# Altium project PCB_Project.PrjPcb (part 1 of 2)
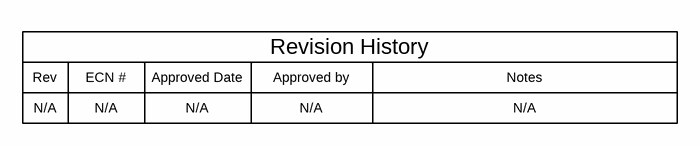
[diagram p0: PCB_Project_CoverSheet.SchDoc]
TID: TIDA-010080; TechSupport: http://www.ti.com/support; SCH_Rev: E1; PRJ_Title: Change in menu Project|Project Options|Parameters; PRJ_Number: TIDA-010080; PRJ_Engineer: Enter name of project lead; PRJ_Customer: Public Release; PCB_Rev: E1; Max Wang: Who did the Layout?; CopyrightYear: 2018
4 sheets, 183 parts. Net scope: global (net labels, ports and power ports of the same name join across sheets).
Board file: PCB_Project_PCB.PcbDoc
Sheets:
  PCB_Project_CoverSheet.SchDoc
  PFC.SchDoc
  LLC.SchDoc
  PCB_Project_EVM_Hardware.SchDoc

## Sheet PCB_Project_CoverSheet.SchDoc
size 431 x 279 mm; Date: Not shown in title block; ApprovedBy: Not shown in title block; CheckedBy: Not shown in title block; Author: Not shown in title block; CompanyName: Not shown in title block; Engineer: Not shown in title block; Organization: Not shown in title block; Address1: Not shown in title block; Address2: Not shown in title block; Address3: Not shown in title block; Address4: Not shown in title block; DocumentNumber: 1; Revision: Use project parameter SCH_Rev; SheetNumber: 1; SheetTotal: 3; PageSetup: Record=PageOptions¦CenterHorizontal=True¦CenterVertical=True¦PrintScale=1.00¦XCorrection=1.00¦YCorrection=1.00¦PrintKind=0¦BorderSize=5000000¦LeftOffset=0¦BottomOffset=0¦Orientation=2¦PaperLength=1000¦PaperWidth=1000¦Scale=100¦PaperSource=15¦PrintQuality=600¦MediaType=1¦DitherType=10¦PaperKind=Letter¦PrintScaleMode=1

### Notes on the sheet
- Rev
- N/A
- ECN #
- Approved Date
- Approved by
- Revision History
- Notes

## Sheet PFC.SchDoc
size 431 x 279 mm; Date: Not shown in title block; ApprovedBy: Not shown in title block; CheckedBy: Not shown in title block; Author: Not shown in title block; CompanyName: Not shown in title block; DrawnBy: Max Wang; Engineer: Max Wang; Organization: Not shown in title block; Address1: Not shown in title block; Address2: Not shown in title block; Address3: Not shown in title block; Address4: Not shown in title block; DocumentNumber: 1; Revision: Use project parameter SCH_Rev; SheetNumber: 2; SheetTotal: 3; PageSetup: Record=PageOptions¦CenterHorizontal=True¦CenterVertical=True¦PrintScale=1.00¦XCorrection=1.00¦YCorrection=1.00¦PrintKind=0¦BorderSize=5000000¦LeftOffset=0¦BottomOffset=0¦Orientation=2¦PaperLength=1000¦PaperWidth=1000¦Scale=100¦PaperSource=15¦PrintQuality=600¦MediaType=1¦DitherType=10¦PaperKind=Letter¦PrintScaleMode=1
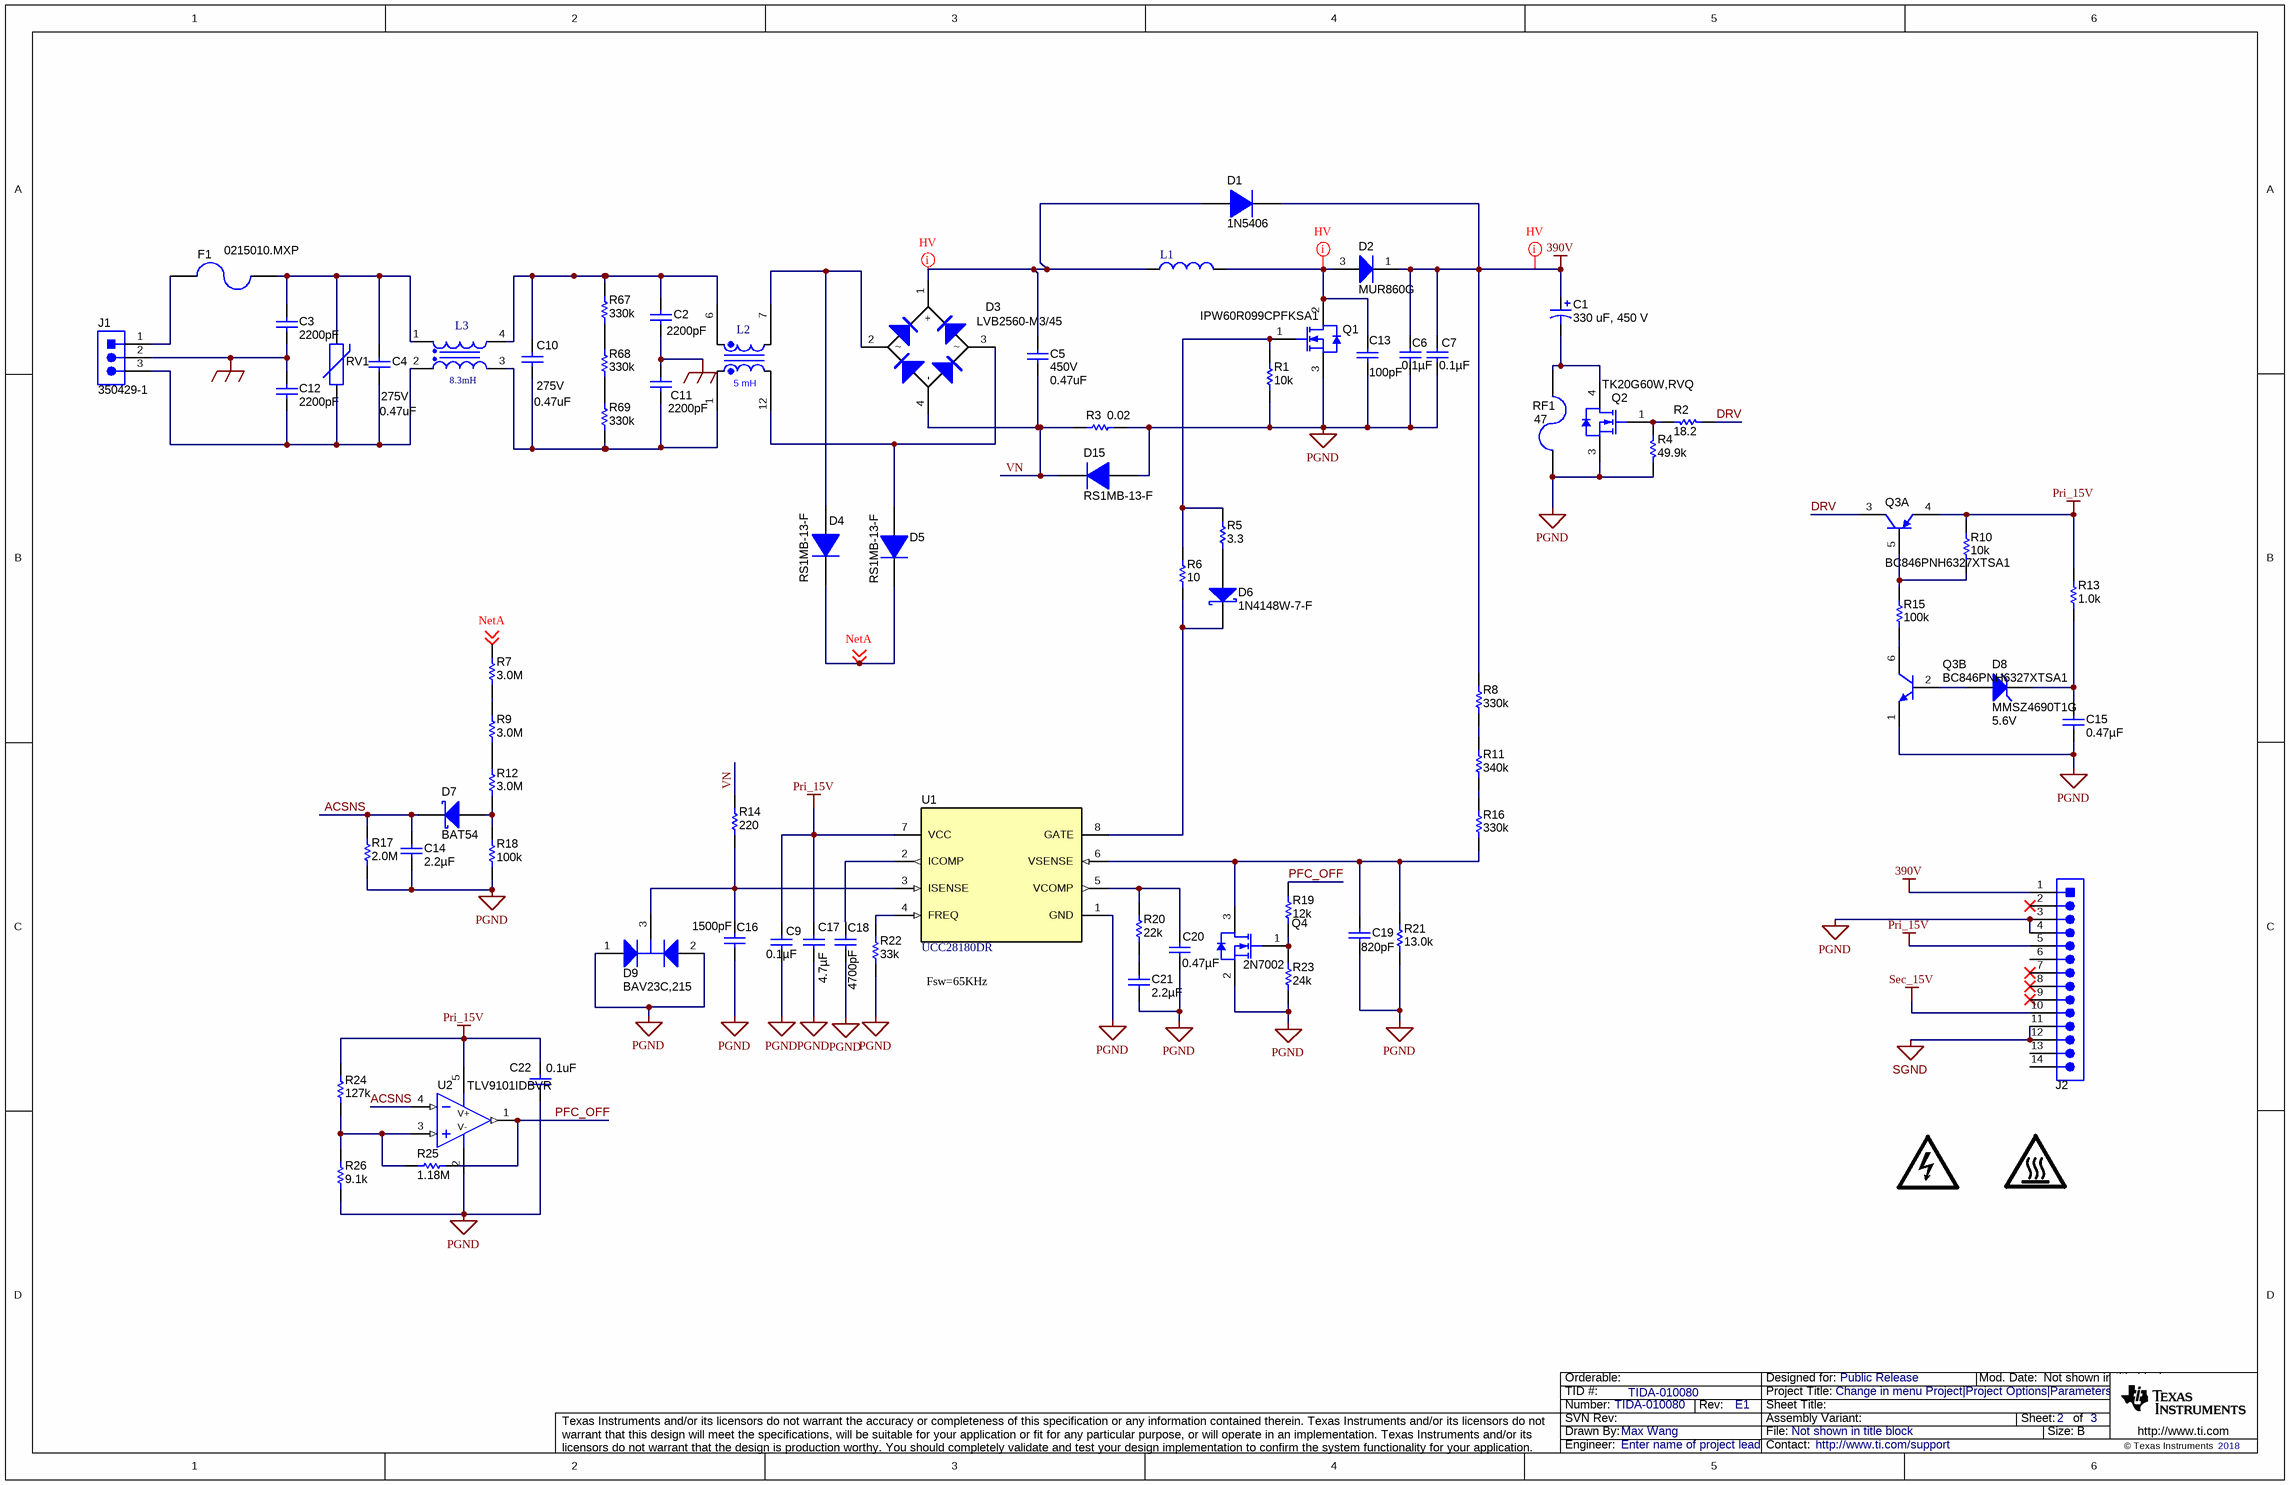
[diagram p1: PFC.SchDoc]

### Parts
(Parts that share a designator on the sheet are numbered #1, #2 ... from top to bottom, then left to right.)
C1  330 uF, 450 V  [WCAP-AIG8_3500x3700]
C2  ValueDisplayed: 2200pF  [AY2_950x500_Straight]  (hidden comment: AY2222M35Y5US63L7)
C3  ValueDisplayed: 2200pF  [AY2_950x500_Straight]  (hidden comment: AY2222M35Y5US63L7)
C4  VDC_V: 275V  ValueDisplayed: 0.47uF  [WCAP-FTX2_1500x1000x1600]  (hidden comment: 890324024005)
C5  VDC_V: 450V  ValueDisplayed: 0.47uF  [B32522_1800x850x1450]  (hidden comment: B32522N6474J)
C6  ValueDisplayed: 0.1µF  [1210_180]  (hidden comment: C3225X7T2J104M160AC)
C7  ValueDisplayed: 0.1µF  [1210_180]  (hidden comment: C3225X7T2J104M160AC)
C9  ValueDisplayed: 0.1µF  [0603]  (hidden comment: GRM188R61E104KA01D)
C10  VDC_V: 275V  ValueDisplayed: 0.47uF  [WCAP-FTX2_1500x1000x1600]  (hidden comment: 890324024005)
C11  ValueDisplayed: 2200pF  [AY2_950x500_Straight]  (hidden comment: AY2222M35Y5US63L7)
C12  ValueDisplayed: 2200pF  [AY2_950x500_Straight]  (hidden comment: AY2222M35Y5US63L7)
C13  ValueDisplayed: 100pF  [1206]  (hidden comment: GRM31A5C2J101JW01D)
C14  ValueDisplayed: 2.2µF  [0603]  (hidden comment: GRM188R6YA225KA12D)
C15  ValueDisplayed: 0.47µF  [0603]  (hidden comment: GCM188R71E474KA64D)
C16  ValueDisplayed: 1500pF  [0603]  (hidden comment: GRM188R71E152KA01D)
C17  ValueDisplayed: 4.7µF  [0603]  (hidden comment: GRM188R61E475KE11D)
C18  ValueDisplayed: 4700pF  [0603]  (hidden comment: GRM188R71C472KA01D)
C19  ValueDisplayed: 820pF  [0603]  (hidden comment: GRM1885C1E821JA01D)
C20  ValueDisplayed: 0.47µF  [0603]  (hidden comment: GRM188R71C474KA88D)
C21  ValueDisplayed: 2.2µF  [0603]  (hidden comment: GRM188Z71C225KE43)
C22  ValueDisplayed: 0.1uF  [0603]  (hidden comment: C1608X7R1H104K080AA)
D1  1N5406  [DO-201AD]
D2  MUR860G  [TO-220AC]
D3  LVB2560-M3/45  [GBJ]
D4  RS1MB-13-F  [SMB]
D5  RS1MB-13-F  [SMB]
D6  1N4148W-7-F  [SOD-123]
D7  Alternate PartNumber: BAT54  [sod-323]  (hidden comment: BAT54HT1G)
D8  MMSZ4690T1G  value 5.6V  [SOD-123]
D9  BAV23C,215  [SOT-23]
D15  RS1MB-13-F  [SMB]
F1  0215010.MXP  [FUSE]
J1  350429-1  [TE_350429-1]
J2  4-644694-4  [aux power]  (value not drawn)
L1  PQ3535  [PFC_L]  (value not drawn)
L2  ValueDisplayed: 5 mH  [WE-CMB_XL]  (hidden comment: 8113-RC)
L3  8.3mH  [WE-CMB_M]
LOGO?#1  DANGER HIGH VOLTAGE  [IEC_HighVoltage_Small]  (value not drawn)  (graphical)
LOGO?#2  CAUTION HOT SURFACE  [IEC_HotSurface_Small]  (value not drawn)  (graphical)
Q1  IPW60R099CPFKSA1  [TO-247]
Q2  TK20G60W,RVQ  [DDPAK]
Q3  BC846PNH6327XTSA1  [SOT-363]  (parts A,B of 2)
Q4  2N7002  [SOT-23]
R1  ValueDisplayed: 10k  [0603]  (hidden comment: CRCW060310K0JNEA)
R2  ValueDisplayed: 18.2  [0805_HV1]  (hidden comment: CRCW080518R2FKEA)
R3  ValueDisplayed: 0.02  [2512]  (hidden comment: CSRN2512FK20L0)
R4  ValueDisplayed: 49.9k  [0603]  (hidden comment: ERJ-3EKF4992V)
R5  ValueDisplayed: 3.3  [0805_HV]  (hidden comment: CRCW08053R30JNEA)
R6  ValueDisplayed: 10  [0805_HV]  (hidden comment: CRCW080510R0JNEA)
R7  ValueDisplayed: 3.0M  [1206]  (hidden comment: CRCW12063M00JNEA)
R8  ValueDisplayed: 330k  [1206]  (hidden comment: CRCW1206330KJNEA)
R9  ValueDisplayed: 3.0M  [1206]  (hidden comment: CRCW12063M00JNEA)
R10  ValueDisplayed: 10k  [0603]  (hidden comment: RC0603JR-0710KL)
R11  ValueDisplayed: 340k  [1206]  (hidden comment: CRCW1206340KFKEA)
R12  ValueDisplayed: 3.0M  [1206]  (hidden comment: CRCW12063M00JNEA)
R13  ValueDisplayed: 1.0k  [0603]  (hidden comment: CRCW06031K00JNEA)
R14  ValueDisplayed: 220  [0603]  (hidden comment: CRCW0603220RJNEA)
R15  ValueDisplayed: 100k  [0603]  (hidden comment: CRCW0603100KJNEA)
R16  ValueDisplayed: 330k  [1206]  (hidden comment: CRCW1206330KJNEA)
R17  ValueDisplayed: 2.0M  [0603]  (hidden comment: CRCW06032M00JNEA)
R18  ValueDisplayed: 100k  [0603]  (hidden comment: CRCW0603100KJNEA)
R19  ValueDisplayed: 12k  [0603]  (hidden comment: CRCW060312K0JNEA)
R20  ValueDisplayed: 22k  [0603]  (hidden comment: CRCW060322K0JNEA)
R21  ValueDisplayed: 13.0k  [0603]  (hidden comment: CRCW060313K0FKEA)
R22  ValueDisplayed: 33k  [0805_HV]  (hidden comment: CRCW080533K0JNEA)
R23  ValueDisplayed: 24k  [0603]  (hidden comment: RC0603JR-0724KL)
R24  ValueDisplayed: 127k  [0603]  (hidden comment: CRCW0603127KFKEA)
R25  ValueDisplayed: 1.18M  [0603]  (hidden comment: CRCW06031M18FKEA)
R26  ValueDisplayed: 9.1k  [0603]  (hidden comment: CRCW06039K10JNEA)
R67  ValueDisplayed: 330k  [1206]  (hidden comment: RC1206FR-07330KL)
R68  ValueDisplayed: 330k  [1206]  (hidden comment: RC1206FR-07330KL)
R69  ValueDisplayed: 330k  [1206]  (hidden comment: RC1206FR-07330KL)
RF1  ValueDisplayed: 47  [inrush res]  (hidden comment: EMC2-47RKI)
RV1  B72210S2271K101  [VAR_S10K275E2]  (value not drawn)
U1  UCC28180DR  [D0008A_N]
U2  PartNumber: TLV9101IDBVR  [DBV0005A_N]  (hidden comment: TLV9101)

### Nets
390V: C1.1(+) C6.1 C7.1 D1.1(K) D2.1(K) J2.1 R8.2
EARTH: C2.2 C3.1 C11.1 C12.1 J1.2
PGND: C6.2 C7.2 C9.2 C13.2 C14.2 C15.2 C16.2 C17.2 C18.2 C19.2 C20.2 C21.2 C22.2 D9.1(A) D9.2(K) D15.2(A) J2.3 J2.4 Q1.3(S) Q2.3(S) Q3.1(E) Q4.2(S) R1.1 R3.2 R4.2 R17.1 R18.1 R21.1 R22.1 R23.1 R26.1 RF1.1 U1.1(GND) U2.2(V-)
Pri_15V: C9.1 C17.1 C22.1 J2.5 Q3.4(E) R10.2 R13.2 R24.2 U1.7(VCC) U2.5(V+)
Sec_15V: J2.10
SGND: J2.11 J2.12
ACSNS: C14.1 D7.1(K) R17.2 U2.4(IN-)
DRV: Q3.3(C) R2.2
NetA: D4.1(K) D5.1(K) R7.2 ; off-sheet NetA
PFC_OFF: R19.2 R25.2 U2.1(OUT)
VN: C5.2 D3.4(-) D15.1(K) R3.1 R14.2
NetC1_2: C1.2(-) Q2.4(D) RF1.2
NetC2_1: C2.1 C10.1 L2.6 L3.4 R67.2
NetC3_2: C3.2 C4.1 F1.1 L3.1 RV1.2
NetC4_2: C4.2 C12.2 J1.3 L3.2 RV1.1
NetC5_1: C5.1 D1.2(A) D3.1(+) L1.1
NetC10_2: C10.2 C11.2 L2.1 L3.3 R69.1
NetC13_1: C13.1 D2.3(A) L1.2 Q1.2(D)
NetC15_1: C15.1 D8.1(K) R13.1
NetC16_1: C16.1 D9.3(C) R14.1 U1.3(ISENSE)
NetC18_1: C18.1 U1.2(ICOMP)
NetC19_1: C19.1 Q4.3(D) R16.1 R21.2 U1.6(VSENSE)
NetC20_1: C20.1 R20.2 U1.5(VCOMP)
NetC21_1: C21.1 R20.1
NetD3_2: D3.2 D4.2(A) L2.7
NetD3_3: D3.3 D5.2(A) L2.12
NetD6_1: D6.1(K) R6.1 U1.8(GATE)
NetD6_2: D6.2(A) R5.1
NetD7_2: D7.2(A) R12.1 R18.2
NetD8_2: D8.2(A) Q3.2(B)
NetF1_2: F1.2 J1.1
NetQ1_1: Q1.1(G) R1.2 R5.2 R6.2
NetQ2_1: Q2.1(G) R2.1 R4.1
NetQ3_5: Q3.5(B) R10.1 R15.2
NetQ3_6: Q3.6(C) R15.1
NetQ4_1: Q4.1(G) R19.1 R23.2
NetR7_1: R7.1 R9.2
NetR8_1: R8.1 R11.2
NetR9_1: R9.1 R12.2
NetR11_1: R11.1 R16.2
NetR22_2: R22.2 U1.4(FREQ)
NetR24_1: R24.1 R25.1 R26.2 U2.3(IN+)
NetR67_1: R67.1 R68.2
NetR68_1: R68.1 R69.2

Not connected (* = marked no-connect by the designer): J2 2* 6 7* 8* 9* 13 14

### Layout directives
net class HV: 390V, NetC5_1, NetC13_1

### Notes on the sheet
- (near U1) 68khz
- (near R22) Fsw=65KHz

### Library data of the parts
C1 = CMP-0009988-2: CAP, AL, 330 uF, 450 V, +/- 20%, TH,  861011486022; Manufacturer: Wurth Elektronik; TaMin_C: -25°C; Polarized: Y; SizeAreaWB_mm2: 1369; Value1: Unknown; U/M: EA; Value: 330uF; TaMax_C: 85°C; SizeZ_mm: 39; SizeX_mm: 35; Cap_Case: 35x37mm; Value2: 450V; SizeArea_mm2: 1225; CompType: Capacitor; AEC Qualified: N; Cap_F: 330µF; IRMS_A: 2.29A; AEC Category: Q200
C2 C3 C11 C12 = AY2222M35Y5US63L7: CAP, CERM, 2200 pF, X1 440 VAC/Y2 300 VAC, +/- 20%, Y5U, AEC-Q200 Grade 1, D9.5xT5mm; Manufacturer: Vishay-Bccomponents; Polarized: N; CompType: Capacitor; Value: 2200pF; U/M: EA; Cap_F: 0.0000000022; Tolerance_%: 20; TaMin_C: -55; TaMax_C: 125; Cap_Case: 9.5x5mm; SizeArea_mm2: 47.5; SizeAreaWB_mm2: 80.5; SizeX_mm: 9.5; SizeY_mm: 5; SizeZ_mm: 14.5; AEC Category: Q200; AEC Qualified: Y; AEC Grade: 1; AC_Safety: X1Y2; VAC_X: 440; VAC_Y: 300
C4 C10 = CMP-0012313-3: CAP, Film, 0.47 uF, 275 V, +/- 10%, TH; Manufacturer: Wurth Elektronik; TaMin_C: -40°C; Polarized: N; SizeAreaWB_mm2: 204; Value1: Unknown; Value: 0.47uF; TaMax_C: 105°C; SizeZ_mm: 16.5; SizeX_mm: 15; SizeY_mm: 10; Cap_Case: 15x10x16mm; SizeArea_mm2: 150; Cap_F: 470nF; AEC Category: Q200
C5 = CMP-0012330-3: CAP, Film, 0.47 uF, 450 V, +/- 5%, AEC-Q200 Grade 1, TH; Manufacturer: TDK; PartNumber: B32522N6474J000; TaMin_C: -55°C; Polarized: N; SizeAreaWB_mm2: 210; Value1: Unknown; Value: 0.47uF; TaMax_C: 125°C; SizeZ_mm: 14.5; SizeX_mm: 18; SizeY_mm: 8.5; Cap_Case: 18x8.5x14.5mm; SizeArea_mm2: 153; AEC Qualified: Y; Cap_F: 470nF; AEC Grade: 1; AEC Category: Q200
C6 C7 = C3225X7T2J104M160AC: CAP, CERM, 0.1 µF, 630 V,+/- 20%, X7T, 1210; Manufacturer: TDK; Polarized: N; CompType: Capacitor; Value: 0.1uF; U/M: EA; Cap_F: 0.0000001; Tolerance_%: 20; VDC_V: 630; Value2: 630V; TaMin_C: -55; TaMax_C: 125; Cap_Case: 1210; SizeArea_mm2: 8; SizeAreaWB_mm2: 14.7; SizeX_mm: 3.2; SizeY_mm: 2.5; SizeZ_mm: 1.8; AEC Category: Q200; Green_Lifecycle: Not Set; Green_REACh: Incomplete
C9 = GRM188R61E104KA01D: CAP, CERM, 0.1 µF, 25 V,+/- 10%, X5R, 0603; Manufacturer: MuRata; Polarized: N; CompType: Capacitor; Value: 0.1uF; U/M: EA; Cap_F: 0.0000001; Tolerance_%: 10; VDC_V: 25; Value2: 25V; TaMin_C: -55; TaMax_C: 85; SizeArea_mm2: 1.28; SizeAreaWB_mm2: 4.68; SizeX_mm: 1.6; SizeY_mm: 0.8; SizeZ_mm: 1; AEC Category: Q200; Green_Lifecycle: Active; Green_REACh: Passed
C13 = GRM31A5C2J101JW01D: CAP, CERM, 100 pF, 630 V,+/- 5%, C0G/NP0, 1206; Manufacturer: MuRata; Polarized: N; CompType: Capacitor; Value: 100pF; U/M: EA; Cap_F: 0.0000000001; Tolerance_%: 5; VDC_V: 630; Value2: 630V; TaMin_C: -55; TaMax_C: 125; SizeArea_mm2: 5.12; SizeAreaWB_mm2: 10.92; SizeX_mm: 3.2; SizeY_mm: 1.6; SizeZ_mm: 1.35; AEC Category: Q200; Green_Lifecycle: Not Set; Green_REACh: Incomplete
C14 = GRM188R6YA225KA12D: CAP, CERM, 2.2 µF, 35 V,+/- 10%, X5R, 0603; Manufacturer: MuRata; Polarized: N; CompType: Capacitor; Value: 2.2uF; U/M: EA; Cap_F: 0.0000022; Tolerance_%: 10; VDC_V: 35; Value2: 35V; TaMin_C: -55; TaMax_C: 85; SizeArea_mm2: 1.28; SizeAreaWB_mm2: 4.68; SizeX_mm: 1.6; SizeY_mm: 0.8; SizeZ_mm: 1; AEC Category: Q200; Green_Lifecycle: Active; Green_REACh: Passed
C15 = GCM188R71E474KA64D: CAP, CERM, 0.47 µF, 25 V,+/- 10%, X7R, AEC-Q200 Grade 1, 0603; Manufacturer: MuRata; Polarized: N; CompType: Capacitor; Value: 0.47uF; U/M: EA; Cap_F: 0.00000047; Tolerance_%: 10; VDC_V: 25; Value2: 25V; TaMin_C: -55; TaMax_C: 125; SizeArea_mm2: 1.28; SizeAreaWB_mm2: 4.68; SizeX_mm: 1.6; SizeY_mm: 0.8; SizeZ_mm: 1; AEC Category: Q200; AEC Qualified: Y
C16 = GRM188R71E152KA01D: CAP, CERM, 1500 pF, 25 V,+/- 10%, X7R, 0603; Manufacturer: MuRata; Polarized: N; CompType: Capacitor; Value: 1500pF; U/M: EA; Cap_F: 0.0000000015; Tolerance_%: 10; VDC_V: 25; Value2: 25V; TaMin_C: -55; TaMax_C: 125; SizeArea_mm2: 1.28; SizeAreaWB_mm2: 4.68; SizeX_mm: 1.6; SizeY_mm: 0.8; SizeZ_mm: 1; AEC Category: Q200; Green_Lifecycle: Active; Green_REACh: Passed
C17 = GRM188R61E475KE11D: CAP, CERM, 4.7 µF, 25 V,+/- 10%, X5R, 0603; Manufacturer: MuRata; Polarized: N; CompType: Capacitor; Value: 4.7uF; U/M: EA; Cap_F: 0.0000047; Tolerance_%: 10; VDC_V: 25; Value2: 25V; TaMin_C: -55; TaMax_C: 85; SizeArea_mm2: 1.28; SizeAreaWB_mm2: 4.68; SizeX_mm: 1.6; SizeY_mm: 0.8; SizeZ_mm: 1; AEC Category: Q200; Green_Lifecycle: Active; Green_REACh: Passed
C18 = GRM188R71C472KA01D: CAP, CERM, 4700 pF, 16 V,+/- 10%, X7R, 0603; Manufacturer: MuRata; Polarized: N; CompType: Capacitor; Value: 4700pF; U/M: EA; Cap_F: 0.0000000047; Tolerance_%: 10; VDC_V: 16; Value2: 16V; TaMin_C: -55; TaMax_C: 125; SizeArea_mm2: 1.28; SizeAreaWB_mm2: 4.68; SizeX_mm: 1.6; SizeY_mm: 0.8; SizeZ_mm: 1; AEC Category: Q200; Green_Lifecycle: Active; Green_REACh: Passed
C19 = GRM1885C1E821JA01D: CAP, CERM, 820 pF, 25 V,+/- 5%, C0G/NP0, 0603; Manufacturer: MuRata; Polarized: N; CompType: Capacitor; Value: 820pF; U/M: EA; Cap_F: 0.00000000082; Tolerance_%: 5; VDC_V: 25; Value2: 25V; TaMin_C: -55; TaMax_C: 125; SizeArea_mm2: 1.28; SizeAreaWB_mm2: 4.68; SizeX_mm: 1.6; SizeY_mm: 0.8; SizeZ_mm: 1; AEC Category: Q200
C20 = GRM188R71C474KA88D: CAP, CERM, 0.47 µF, 16 V,+/- 10%, X7R, 0603; Manufacturer: MuRata; Polarized: N; CompType: Capacitor; Value: 0.47uF; U/M: EA; Cap_F: 0.00000047; Tolerance_%: 10; VDC_V: 16; Value2: 16V; TaMin_C: -55; TaMax_C: 125; SizeArea_mm2: 1.28; SizeAreaWB_mm2: 4.68; SizeX_mm: 1.6; SizeY_mm: 0.8; SizeZ_mm: 1; AEC Category: Q200; Green_Lifecycle: Active; Green_REACh: Passed
C21 = GRM188Z71C225KE43: CAP, CERM, 2.2 µF, 16 V,+/- 10%, X7R, 0603; Manufacturer: MuRata; Polarized: N; CompType: Capacitor; Value: 2.2uF; U/M: EA; Cap_F: 0.0000022; Tolerance_%: 10; VDC_V: 16; Value2: 16V; TaMin_C: -55; TaMax_C: 125; SizeArea_mm2: 1.28; SizeAreaWB_mm2: 4.68; SizeX_mm: 1.6; SizeY_mm: 0.8; SizeZ_mm: 1; AEC Category: Q200; Green_Lifecycle: Active; Green_REACh: Passed
C22 = CMP-0007044-5: CAP, CERM, 0.1 uF, 50 V, +/- 10%, X7R, 0603; Manufacturer: TDK; TaMin_C: -55°C; ESR_ohm: 0.0296; Polarized: N; SizeAreaWB_mm2: 4.68; Value1: 0.0296 ohm; U/M: EA; Value: 0.1uF; TaMax_C: 125°C; SizeZ_mm: 1; SizeX_mm: 1.6; SizeY_mm: 0.8; Value2: 50V; SizeArea_mm2: 1.28; CompType: Capacitor; Cap_F: 100nF; IRMS_A: 9.7199dA; AEC Category: Q200
D1 = 1N5406: Diode, Switching-Bridge, 600 V, 3 A, TH; Manufacturer: Vishay-Semiconductor; U/M: EA; Vf_V: 1.2; Value: 600V; Value1: 3A; Value2: 1.2V; Io_A: 3; Vr_V: 600; TJmax_C: 150; SizeAreaWB_mm2: 166.38; SizeArea_mm2: 109.08; SizeX_mm: 21.6; SizeY_mm: 5.05; SizeZ_mm: 5.3; AEC Category: Q101; Green_Lifecycle: Not Set; Green_REACh: Incomplete
D2 = MUR860G: Diode, Ultrafast, 600 V, 8 A, TH; Manufacturer: ON Semiconductor; SymbolCreator: a0412235; U/M: EA; Vf_V: 0.98; Value: 600V; Value1: 8A; Value2: 0.98V; Io_A: 8; Vr_V: 600; TJmax_C: 175; RJC_CperW: 4.75; SizeAreaWB_mm2: 78.975; SizeArea_mm2: 45.675; SizeX_mm: 10.15; SizeY_mm: 4.5; SizeZ_mm: 23; AEC Category: Q101; Green_Lifecycle: Not Set; Green_REACh: Incomplete
D3 = GBJ2510-F: Diode, Switching-Bridge, 600 V, 25 A, TH; Manufacturer: Vishay; U/M: EA; Vf_V: 1.05; Value: 1000V; Value1: 25A; Value2: 1.05V; Io_A: 25; Vr_V: 1000; TJmax_C: 150; RJC_CperW: 0.6; SizeAreaWB_mm2: 211.2; SizeArea_mm2: 138; SizeX_mm: 30; SizeY_mm: 4.6; SizeZ_mm: 24; AEC Category: Q101; AEC Qualified: N
D4 D5 D15 = RS1MB-13-F: Diode, P-N, 1000 V, 1 A, SMB; Manufacturer: Diodes Inc.; U/M: EA; Vf_V: 1.3; Value: 1000V; Value1: 1A; Value2: 1.3V; Io_A: 1; Vr_V: 1000; TJmax_C: 150; RJC_CperW: 20; SizeAreaWB_mm2: 44.156; SizeArea_mm2: 21.336; SizeX_mm: 5.6; SizeY_mm: 3.81; SizeZ_mm: 2.6; AEC Category: Q101; Green_Lifecycle: Active; Green_REACh: Passed
D6 = CMP-0028358-1: Diode, Schottky, 70 V, 0.015 A, SOD-123; Manufacturer: Diodes Inc.; PartNumber: 1N5711W-7-F; Io_A: 15mA; Green_Lifecycle: Not Set; SizeAreaWB_mm2: 13.095; Vr_V: 70V; Green_REACh: Incomplete; Value1: 0.015A; U/M: EA; Value: 70V; SizeZ_mm: 1.35; SizeX_mm: 3.85; SizeY_mm: 1.7; Vf_V: 1V; SizeArea_mm2: 6.545; AEC Category: Q101
D7 = BAT54HT1G: Diode, Schottky, 30V, 0.2A, SOD-323; Manufacturer: ON Semiconductor; U/M: EA; Vf_V: 0.35; Value2: 0.35V; Io_A: 0.2; Vr_V: 30
D8 = MMSZ4690T1G: Diode, Zener, 5.6 V, 500 mW, SOD-123; Manufacturer: ON Semiconductor; SymbolCreator: a0412235; U/M: EA; Power_W: 0.5; Vz_V: 5.6; Value1: 0.5W; RJA_CperW: 340; SizeAreaWB_mm2: 13.095; SizeArea_mm2: 6.545; SizeX_mm: 3.85; SizeY_mm: 1.7; SizeZ_mm: 1.35; AEC Category: Q101; Green_Lifecycle: Active; Green_REACh: Passed
D9 = BAV23C,215: Diode, Switching, 250 V, 0.225 A, SOT-23; Manufacturer: Nexperia; SymbolCreator: a0412235; U/M: EA; Vf_V: 1.25; Value: 250V; Value1: 0.225A; Value2: 1.25V; Io_A: 0.225; Vr_V: 250; TJmax_C: 150; SizeAreaWB_mm2: 14; SizeArea_mm2: 7.5; SizeX_mm: 2.5; SizeY_mm: 3; SizeZ_mm: 1.1; AEC Category: Q101; AEC Qualified: N; Green_Lifecycle: Not Set; Green_REACh: Incomplete
F1 = 0678L9150-02: Fuse, 10 A, 250 VAC; Manufacturer: Bel Fuse; SizeAreaWB_mm2: 59.59; SizeArea_mm2: 29.89; SizeX_mm: 9.8; SizeY_mm: 3.05; SizeZ_mm: 3.18; VDC_V: 72; VAC_V: 250; Irating_A: 15; Rtyp_Ohm: 0.0036; MeltingTyp: 110
J1 = 350429-1: Header(Shrouded), 6.35mm, 3x1, Tin, TH; Manufacturer: TE Connectivity; SymbolCreator: a0799628; Pitch_mm: 6.35; Gender: Male; Shrouded: Y; Row_Count: 1; Current_A: 12; Voltage_V: 600
J2 = 4-644694-4: Header, 100 mil, 14x1, Tin, R/A, TH; Manufacturer: TE Connectivity; SymbolCreator: a0411947; Pitch_mm: 2.54; Gender: Male; Shrouded: N; Row_Count: 1; Cert_CSA: Y
L1 = Inductor: Part Number: 750344651; Code_IEC: 1005
L2 = 7448258022: Common Mode Filters / Chokes 5mH MIN; Manufacturer: Bourns; SymbolCreator: a0799628; CompType: Coupled Inductor; DCR_ohm: 22 mOhms; Isat: 8.9 A; Tolerance_%: 30
L3 = 7448051804: 8.3mH @ 10kHz 2 Line Common Mode Choke Through Hole DCR 12mOhm; DC Resistance max.: 4.2mOhm; Insulation Test Voltage: 1500V (AC); Inductance: 4.5mH; Rated Voltage: 250V (AC); Rated Current: 18A
LOGO?#1 = IEC_HighVoltage: IEC 61010-1 High Voltage Warning; SymbolCreator: a0412235
LOGO?#2 = IEC_HotSurface: IEC 61010-1 Hot Surface Warning; SymbolCreator: a0412235
Q1 = IPW60R099CPFKSA1: MOSFET, N-CH, 600 V, 31 A, TO-247; Manufacturer: Infineon Technologies; Alternate Manufacturer: None; U/M: EA; ChType: N; Value: 600V; VdsMax_V: 600; Value1: ? ohm; Value2: 60 nC; QgTyp_nC: 60; Vgs_V: 20; IdsMax_A: 31; SizeAreaWB_mm2: 123.2; SizeArea_mm2: 78; SizeX_mm: 15.6; SizeY_mm: 5; SizeZ_mm: 25; AEC Category: Q101
Q2 = AOB20S60L: MOSFET, N-CH, 600 V, 20 A, DDPAK; Manufacturer: AOS; Alternate Manufacturer: None; U/M: EA; ChType: N; Value: 600V; VdsMax_V: 600; Value1: ? ohm; Value2: 19.8 nC; QgTyp_nC: 19.8; Vgs_V: 30; IdsMax_A: 20; SizeAreaWB_mm2: 209.6992; SizeArea_mm2: 154.8892; SizeX_mm: 15.245; SizeY_mm: 10.16; SizeZ_mm: 4.445; AEC Category: Q101; Green_Lifecycle: Not Set; Green_REACh: Incomplete
Q3 = BC 846PN H6327, Infineon Technologies: Transistor, NPN/PNP Pair, 65 V, 0.1 A, SOT-363; SymbolCreator: a0411947; PNP: 1; Vceo_V: 65; Vcesat1_V: 0.2; Value: 65 V; IcRated_A: 0.1; Value1: 0.1 A; HfeMax: 450; TaMin_C: -65; TaMax_C: 150; SizeAreaWB_mm2: 10.24; SizeArea_mm2: 4.84; SizeX_mm: 2.2; SizeZ_mm: 1.1; CompType: BJT; U/M: EA; AEC Category: Q101; AEC Qualified: N
Q4 = 2N7002: MOSFET, N-CH, 60 V, 115 A, SOT-23; Manufacturer: Fairchild Semiconductor; Alternate Manufacturer: None; U/M: EA; ChType: N; Value: 60V; VdsMax_V: 60; Value1: ? ohm; Value2: ? nC; Vgs_V: 20; IdsMax_A: 115; SizeAreaWB_mm2: 14; SizeArea_mm2: 7.5; SizeX_mm: 2.5; SizeY_mm: 3; SizeZ_mm: 1.1; AEC Category: Q101; Green_Lifecycle: Active; Green_REACh: Passed
R1 = CRCW060310K0JNEA: RES, 10 k, 5%, 0.1 W, 0603; Manufacturer: Vishay-Dale; CompType: Resistor; Value: 10k; Res_ohm: 10000; Value_Code: 10k0; Tolerance_%: 5; Power_W: 0.1; Value2: 0.1W; VDC_V: 75; TempCo: 200 ppm/C; SizeArea_mm2: 1.28; SizeX_mm: 1.6; SizeY_mm: 0.8; SizeZ_mm: 1; EIA_Code: E24; U/M: EA; AEC Category: Q200; Green_Lifecycle: Active; Green_REACh: Passed
R2 = CRCW080518R2FKEA: RES, 18.2, 1%, 0.125 W, 0805; Manufacturer: Vishay-Dale; CompType: Resistor; Value: 18.2; Value_Code: 18R2; Tolerance_%: 1; Power_W: 0.125; Value2: 0.125W; VDC_V: 150; TempCo: 100 ppm/C; SizeArea_mm2: 2.5; SizeX_mm: 2; SizeY_mm: 1.25; SizeZ_mm: 1.45; EIA_Code: E96; U/M: EA; AEC Category: Q200
R3 = CSRN2512FK20L0: RES, 0.02, 1%, 2 W, 2512; Manufacturer: Stackpole Electronics Inc; CompType: Resistor; Value: 0.02; Value_Code: R020; Tolerance_%: 1; Power_W: 2; Value2: 2W; TempCo: 200 ppm/C; SizeArea_mm2: 20.16; SizeX_mm: 6.3; SizeY_mm: 3.2; SizeZ_mm: 0.71; EIA_Code: E96; U/M: EA; AEC Category: Q200; Green_Lifecycle: Active; Green_REACh: Passed
R4 = CMP-0022705-3: RES, 49.9 k, 1%, 0.1 W, AEC-Q200 Grade 0, 0603; Manufacturer: Panasonic; Power_W: 100mW; TempCo: 100 ppm/C; Value_Code: 49k9; U/M: EA; Value: 49.9k; EIA_Code: E96; SizeX_mm: 1.6; SizeY_mm: 0.8; SizeZ_mm: 1; Value2: 0.1W; SizeArea_mm2: 1.28; AEC Qualified: Y; VDC_V: 75V; AEC Grade: 0; AEC Category: Q200
R5 = CRCW08053R30JNEA: RES, 3.3, 5%, 0.125 W, 0805; Manufacturer: Vishay-Dale; CompType: Resistor; Value: 3.3; Value_Code: 3R30; Tolerance_%: 5; Power_W: 0.125; Value2: 0.125W; VDC_V: 150; TempCo: 200 ppm/C; SizeArea_mm2: 2.5; SizeX_mm: 2; SizeY_mm: 1.25; SizeZ_mm: 1.45; EIA_Code: E24; U/M: EA; AEC Category: Q200
R6 = CRCW080510R0JNEA: RES, 10, 5%, 0.125 W, 0805; Manufacturer: Vishay-Dale; CompType: Resistor; Value: 10; Value_Code: 10R0; Tolerance_%: 5; Power_W: 0.125; Value2: 0.125W; VDC_V: 150; TempCo: 200 ppm/C; SizeArea_mm2: 2.5; SizeX_mm: 2; SizeY_mm: 1.25; SizeZ_mm: 1.45; EIA_Code: E24; U/M: EA; AEC Category: Q200; Green_Lifecycle: Active; Green_REACh: Passed
R7 R9 R12 = CRCW12063M00JNEA: RES, 3.0 M, 5%, 0.25 W, 1206; Manufacturer: Vishay-Dale; CompType: Resistor; Value: 3.0Meg; Res_ohm: 3000000; Value_Code: 3M00; Tolerance_%: 5; Power_W: 0.25; Value2: 0.25W; VDC_V: 200; TempCo: 200 ppm/C; SizeArea_mm2: 5.12; SizeX_mm: 3.2; SizeY_mm: 1.6; SizeZ_mm: 1.35; EIA_Code: E24; U/M: EA; AEC Category: Q200
R8 R16 = CRCW1206330KJNEA: RES, 330 k, 5%, 0.25 W, 1206; Manufacturer: Vishay-Dale; CompType: Resistor; Value: 330k; Res_ohm: 330000; Tolerance_%: 5; Power_W: 0.25; Value2: 0.25W; VDC_V: 200; TempCo: 200 ppm/C; SizeArea_mm2: 5.12; SizeX_mm: 3.2; SizeY_mm: 1.6; SizeZ_mm: 1.35; EIA_Code: E24; U/M: EA; AEC Category: Q200
R10 = RC0603JR-0710KL: RES, 10 k, 5%, 0.1 W, 0603; Manufacturer: Yageo America; CompType: Resistor; Value: 10k; Res_ohm: 10000; Value_Code: 10k0; Tolerance_%: 5; Power_W: 0.1; Value2: 0.1W; VDC_V: 50; TempCo: 100 ppm/C; SizeArea_mm2: 1.28; SizeX_mm: 1.6; SizeY_mm: 0.8; SizeZ_mm: 1; EIA_Code: E24; U/M: EA; AEC Category: Q200; Green_Lifecycle: Active; Green_REACh: Passed
R11 = CRCW1206340KFKEA: RES, 340 k, 1%, 0.25 W, 1206; Manufacturer: Vishay-Dale; CompType: Resistor; Value: 340k; Res_ohm: 340000; Tolerance_%: 1; Power_W: 0.25; Value2: 0.25W; VDC_V: 200; TempCo: 100 ppm/C; SizeArea_mm2: 5.12; SizeX_mm: 3.2; SizeY_mm: 1.6; SizeZ_mm: 1.35; EIA_Code: E96; U/M: EA; AEC Category: Q200
R13 = CRCW06031K00JNEA: RES, 1.0 k, 5%, 0.1 W, 0603; Manufacturer: Vishay-Dale; CompType: Resistor; Value: 1.0k; Res_ohm: 1000; Value_Code: 1k00; Tolerance_%: 5; Power_W: 0.1; Value2: 0.1W; VDC_V: 75; TempCo: 200 ppm/C; SizeArea_mm2: 1.28; SizeX_mm: 1.6; SizeY_mm: 0.8; SizeZ_mm: 1; EIA_Code: E24; U/M: EA; AEC Category: Q200; Green_Lifecycle: Active; Green_REACh: Passed
R14 = CRCW0603220RJNEA: RES, 220, 5%, 0.1 W, 0603; Manufacturer: Vishay-Dale; CompType: Resistor; Value: 220; Value_Code: 220R; Tolerance_%: 5; Power_W: 0.1; Value2: 0.1W; VDC_V: 75; TempCo: 200 ppm/C; SizeArea_mm2: 1.28; SizeX_mm: 1.6; SizeY_mm: 0.8; SizeZ_mm: 1; EIA_Code: E24; U/M: EA; AEC Category: Q200; Green_Lifecycle: Active; Green_REACh: Passed
R15 R18 = CRCW0603100KJNEA: RES, 100 k, 5%, 0.1 W, 0603; Manufacturer: Vishay-Dale; CompType: Resistor; Value: 100k; Res_ohm: 100000; Tolerance_%: 5; Power_W: 0.1; Value2: 0.1W; VDC_V: 75; TempCo: 200 ppm/C; SizeArea_mm2: 1.28; SizeX_mm: 1.6; SizeY_mm: 0.8; SizeZ_mm: 1; EIA_Code: E24; U/M: EA; AEC Category: Q200; Green_Lifecycle: Active; Green_REACh: Passed
R17 = CRCW06032M00JNEA: RES, 2.0 M, 5%, 0.1 W, 0603; Manufacturer: Vishay-Dale; CompType: Resistor; Value: 2.0Meg; Res_ohm: 2000000; Value_Code: 2M00; Tolerance_%: 5; Power_W: 0.1; Value2: 0.1W; VDC_V: 75; TempCo: 200 ppm/C; SizeArea_mm2: 1.28; SizeX_mm: 1.6; SizeY_mm: 0.8; SizeZ_mm: 1; EIA_Code: E24; U/M: EA; AEC Category: Q200
R19 = CRCW060312K0JNEA: RES, 12 k, 5%, 0.1 W, 0603; Manufacturer: Vishay-Dale; CompType: Resistor; Value: 12k; Res_ohm: 12000; Value_Code: 12k0; Tolerance_%: 5; Power_W: 0.1; Value2: 0.1W; VDC_V: 75; TempCo: 200 ppm/C; SizeArea_mm2: 1.28; SizeX_mm: 1.6; SizeY_mm: 0.8; SizeZ_mm: 1; EIA_Code: E24; U/M: EA; AEC Category: Q200; Green_Lifecycle: Active; Green_REACh: Passed
R20 = CRCW060322K0JNEA: RES, 22 k, 5%, 0.1 W, 0603; Manufacturer: Vishay-Dale; CompType: Resistor; Value: 22k; Res_ohm: 22000; Value_Code: 22k0; Tolerance_%: 5; Power_W: 0.1; Value2: 0.1W; VDC_V: 75; TempCo: 200 ppm/C; SizeArea_mm2: 1.28; SizeX_mm: 1.6; SizeY_mm: 0.8; SizeZ_mm: 1; EIA_Code: E24; U/M: EA; AEC Category: Q200; Green_Lifecycle: Active; Green_REACh: Passed
R21 = CRCW060313K0FKEA: RES, 13.0 k, 1%, 0.1 W, 0603; Manufacturer: Vishay-Dale; CompType: Resistor; Value: 13.0k; Res_ohm: 13000; Value_Code: 13k0; Tolerance_%: 1; Power_W: 0.1; Value2: 0.1W; VDC_V: 75; TempCo: 100 ppm/C; SizeArea_mm2: 1.28; SizeX_mm: 1.6; SizeY_mm: 0.8; EIA_Code: E96; U/M: EA; AEC Category: Q200; Green_Lifecycle: Active; Green_REACh: Passed
R22 = CRCW080533K0JNEA: RES, 33 k, 5%, 0.125 W, 0805; Manufacturer: Vishay-Dale; CompType: Resistor; Value: 33k; Res_ohm: 33000; Value_Code: 33k0; Tolerance_%: 5; Power_W: 0.125; Value2: 0.125W; VDC_V: 150; TempCo: 200 ppm/C; SizeArea_mm2: 2.5; SizeX_mm: 2; SizeY_mm: 1.25; SizeZ_mm: 1.45; EIA_Code: E24; U/M: EA; AEC Category: Q200
R23 = RC0603JR-0724KL: RES, 24 k, 5%, 0.1 W, 0603; Manufacturer: Yageo America; CompType: Resistor; Value: 24k; Res_ohm: 24000; Value_Code: 24k0; Tolerance_%: 5; Power_W: 0.1; Value2: 0.1W; VDC_V: 50; TempCo: 100 ppm/C; SizeArea_mm2: 1.28; SizeX_mm: 1.6; SizeY_mm: 0.8; SizeZ_mm: 1; EIA_Code: E24; U/M: EA; AEC Category: Q200
R24 = CRCW0603127KFKEA: RES, 127 k, 1%, 0.1 W, 0603; Manufacturer: Vishay-Dale; CompType: Resistor; Value: 127k; Res_ohm: 127000; Tolerance_%: 1; Power_W: 0.1; Value2: 0.1W; VDC_V: 75; TempCo: 100 ppm/C; SizeArea_mm2: 1.28; SizeX_mm: 1.6; SizeY_mm: 0.8; EIA_Code: E96; U/M: EA; AEC Category: Q200; Green_Lifecycle: Active; Green_REACh: Passed
R25 = CRCW06031M18FKEA: RES, 1.18 M, 1%, 0.1 W, 0603; Manufacturer: Vishay-Dale; CompType: Resistor; Value: 1.18Meg; Res_ohm: 1180000; Value_Code: 1M18; Tolerance_%: 1; Power_W: 0.1; Value2: 0.1W; VDC_V: 75; TempCo: 100 ppm/C; SizeArea_mm2: 1.28; SizeX_mm: 1.6; SizeY_mm: 0.8; EIA_Code: E96; U/M: EA; AEC Category: Q200
R26 = CRCW06039K10JNEA: RES, 9.1 k, 5%, 0.1 W, 0603; Manufacturer: Vishay-Dale; CompType: Resistor; Value: 9.1k; Res_ohm: 9100; Value_Code: 9k10; Tolerance_%: 5; Power_W: 0.1; Value2: 0.1W; VDC_V: 75; TempCo: 200 ppm/C; SizeArea_mm2: 1.28; SizeX_mm: 1.6; SizeY_mm: 0.8; SizeZ_mm: 1; EIA_Code: E24; U/M: EA; AEC Category: Q200; Green_Lifecycle: Active; Green_REACh: Passed
R67-R69 = CMP-0018205-2: RES, 330 k, 1%, 0.25 W, 1206; Manufacturer: Yageo America; Power_W: 250mW; TempCo: 100 ppm/C; U/M: EA; Value: 330k; SizeX_mm: 3.2; SizeY_mm: 1.6; SizeZ_mm: 1.35; Value2: 0.25W; SizeArea_mm2: 5.12; VDC_V: 200V; AEC Category: Q200
RF1 = EMC2-47RKI: RES, 47, 10%, 2 W, Axial resistor; Manufacturer: TT Electronics/IRC; SymbolCreator: a0412235; CompType: Fusible Resistor; Value: 47; Value_Code: 47R0; Tolerance_%: 10; Power_W: 2; Value2: 2W; TempCo: 100 ppm/C; U/M: EA; AEC Category: Q200; Green_Lifecycle: Not Set; Green_REACh: Incomplete
RV1 = S10K275E2: Varistor 275V RMS 10MM Radial, TH; Manufacturer: TDK; SymbolCreator: a0412235; SizeAreaWB_mm2: 103.6; SizeArea_mm2: 64.8; SizeX_mm: 12; SizeY_mm: 5.4; SizeZ_mm: 14.5; Green_Lifecycle: Not Set; Green_REACh: Incomplete
U1 = CMP-0074100-1: 8-PIN CONTINUOUS CONDUCTION MODE (CCM) PFC CONTROLLER, D0008A (SOIC-8); Alternate Manufacturer: Texas Instruments; SizeAreaWB_mm2: 56.58; U/M: EA; SizeZ_mm: 1.75; SizeX_mm: 4.9; SizeY_mm: 6.2; SizeArea_mm2: 30.38; CompType: IC
U2 = CMP-0073526-1: 36V, Low-Power, RRO, General-Purpose Operational Amplifier, DBV0005A (SOT-23-5); Alternate PartNumber: TLV171IDBVT; Alternate Manufacturer: Texas Instruments; SizeAreaWB_mm2: 14.82; U/M: EA; SizeZ_mm: 1.45; SizeX_mm: 2.8; SizeY_mm: 2.9; SizeArea_mm2: 8.12; CompType: IC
